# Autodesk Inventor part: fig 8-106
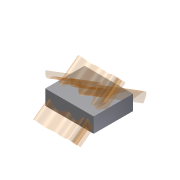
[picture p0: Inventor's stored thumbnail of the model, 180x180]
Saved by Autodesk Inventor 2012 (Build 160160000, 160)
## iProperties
Shininess: 64.0
Length Units: 11269
Angle Units: 11279
Time Units: 11290
Mass Units: 11283
Length Display Precision: 3
Angle Display Precision: 2
Compacted: True
Part Number: fig 8-106
Document SubType Name: Modeling
Created: 2002-12
Designer: deepak
Density: 1 g/cm^3
Material: Default
Density: 0.0
Volumn: 0.0
Area: 0.0
PropertySet Name: Model Information
Control State: 0
Master: False
Checked Out: False
Author: deepak
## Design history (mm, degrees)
sketch "Sketch1"
  geometry: L1 (-33.715, 26.527)-(30.916, 26.527); L2 (30.916, 26.527)-(30.916, -25.891); L3 (30.916, -25.891)-(-33.715, -25.891); L4 (-33.715, -25.891)-(-33.715, 26.527)
  constraints: 8 end point, 2 parallel, 1 horizontal, 1 perpendicular
extrude "Extrusion1" new body sketch "Sketch1" distance "d0" = 20; taper "d1" = 0 deg
sketch "Sketch2"
  geometry: L1 (-44.187, -5.757)-(15.849, 38.63)
  constraints: 2 end point
workplane "Work Plane1"
sketch "Sketch3"
  geometry: L1 (33.715, -6.248)-(33.715, 9.834) reference; L2 (-30.916, -6.248)-(-30.916, 9.834) reference; 10 further points
  constraints: 2 point on line, 11 other
feature "SweepSrf1" sketch "Sketch3" dims "d2" = 0
sketch "Sketch4"
  geometry: L1 (-26.819, 39.395)-(38.245, -1.181)
  constraints: 2 end point
workplane "Work Plane2"
sketch "Sketch5"
  geometry: L1 (-30.916, -5.198)-(-30.916, 11.772) reference; L2 (33.715, -5.198)-(33.715, 11.772) reference; 10 further points
  constraints: 2 point on line, 10 other
feature "SweepSrf2" sketch "Sketch5" dims "d3" = 0
body "Solid1"
body "Srf1"
body "Srf2"
